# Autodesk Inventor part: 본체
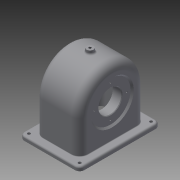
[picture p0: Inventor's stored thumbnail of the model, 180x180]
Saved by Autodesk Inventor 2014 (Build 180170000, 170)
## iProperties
Created: 2016-01
Part Number: 본체
Material: Generic
Document SubType Name: Modeling
Designer: 04
Density: 1 g/cm^3
Appearance: Default
Author: 04
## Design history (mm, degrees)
sketch "스케치1"
  geometry: L1 (-57, 0)-(-57, 64); L2 (57, 64)-(57, 0); L3 (57, 0)-(-57, 0); A1 r 57 centre (0, 64) between (57, 64) and (-57, 64); 2 further points
  constraints: 6 end point, 2 point on circle, 2 tangent, 1 centre point, 1 coincident, 1 midpoint, 1 parallel, 1 perpendicular, 1 vertical
  dimensions: "d0" = 64 distance of L1.start L1.end; "d2" = 114 distance of L2.end L1.start
extrude "돌출1" new body sketch "스케치1" stored distance "d3" = 77; taper "d4" = 0 deg
sketch "스케치3"
  geometry: L1 (-57, 0)-(-57, 64) reference; L2 (57, 0)-(-57, 0) reference; L3 (57, 64)-(57, 0) reference; L4 (51, 64)-(51, 0); L5 (-51, 0)-(-51, 64); A1 r 57 centre (0, 64) between (57, 64) and (-57, 64) reference; A2 r 51 centre (0, 64) between (51, 64) and (-51, 64); 1 further point
  constraints: 4 end point, 2 point on circle, 2 point on line, 1 centre point, 1 parallel, 1 perpendicular, 1 tangent
  dimensions: "d5" = 6 distance between parallel lines of L1 L5; "d6" = 6 distance between parallel lines of L3 L4
extrude "돌출2" cut sketch "스케치3" stored distance "d7" = 67; taper "d8" = 0 deg
sketch "스케치4"
  geometry: L1 (72, -6)-(72, -108) reference; L2 (72, -108)-(5, -108) reference; L3 (5, -108)-(5, -6) reference; L4 (5, -6)-(72, -6) reference; L5 (90.5, -127)-(-13.5, -127); L6 (-13.5, -127)-(-13.5, 13); L7 (-13.5, 13)-(90.5, 13); L8 (90.5, 13)-(90.5, -127); L9 (90.5, -127)-(-13.5, 13); L10 (-13.5, -127)-(90.5, 13); 1 further point
  constraints: 12 end point, 2 midpoint, 2 parallel, 1 horizontal, 1 perpendicular
  dimensions: "d9" = 104 distance of L6.end L7.end; "d10" = 140 distance of L5.end L6.end
extrude "돌출3" join sketch "스케치4" distance "d11" = 7; taper "d12" = 0 deg
sketch "스케치6"
  geometry: 1 further point
sketch "스케치7"
  geometry: C1 r 31 at (64, 0); A1 r 57 centre (64, 0) between (64, -57) and (64, 57) reference; 1 further point
  constraints: 1 centre point, 1 coincident
  dimensions: "d86" = 62 diameter of C1
extrude "돌출4" join sketch "스케치7" distance "d14" = 10; taper "d15" = 0 deg
sketch "스케치8"
  geometry: L1 (-33.5, 115)-(-33.5, 64) reference; L2 (-33.5, 64)-(-33.5, 0) reference; L3 (48.5, 33)-(48.5, 95) reference; L4 (48.5, 64)-(-33.5, 64); L5 (-38.5, 121)-(-38.5, 64) reference; L6 (-38.5, 64)-(-38.5, 7) reference; L7 (-38.5, 107.943)-(-19.5, 92); L8 (-19.5, 92)-(-19.5, 64); L9 (-19.5, 64)-(-38.5, 64); 3 further points
  constraints: 8 end point, 2 perpendicular, 2 point on line, 1 collinear, 1 midpoint
  dimensions: "d18" = 50 deg angle of L8 L7; "d19" = 19 distance between parallel lines of L5 L8; "d20" = 28 distance of L7.end L8.end
revolve "회전1" sketch "스케치8" stored, may be unused: angle "d21" = 90 deg
sketch "스케치9"
  geometry: L1 (-38.5, 121)-(-38.5, 64) reference; L2 (-38.5, 64)-(-38.5, 7) reference; L3 (48.5, 33)-(48.5, 95) reference; L4 (48.5, 64)-(-38.5, 64); L5 (-33.5, 103.747)-(-19.5, 92) reference; L6 (-38.5, 101.416)-(-35.5, 98.899); L7 (-38.5, 101.416)-(-38.5, 64); L8 (-35.5, 64)-(-35.5, 98.899); L9 (-38.5, 64)-(-35.5, 64); 2 further points
  constraints: 10 end point, 2 collinear, 2 parallel, 2 point on line, 1 midpoint, 1 perpendicular
  dimensions: "d22" = 5 distance between parallel lines of L5 L6; "d23" = 3 distance between parallel lines of L7 L8
revolve "회전2" sketch "스케치9" stored, may be unused: angle "d24" = 90 deg
sketch "스케치10"
  geometry: C1 r 31 at (0, 0) reference; C2 r 20 at (0, 0); 1 further point
  constraints: 1 centre point, 1 coincident
  dimensions: "d25" = 40 diameter of C2
extrude "돌출5" cut sketch "스케치10" stored distance "d26" = 10; taper "d27" = 0 deg
sketch "스케치11"
  geometry: C1 r 20 at (0, 0) reference; 2 further points
  constraints: 1 horizontal alignment
  dimensions: "d28" = 28 distance of C1.centre point (-28, 0)
sketch "스케치12"
  geometry: C1 r 20 at (0, 0) reference; 2 further points
  constraints: 1 horizontal alignment
  dimensions: "d29" = 24 distance of C1.centre point (24, 0)
hole "구멍1" sketch "스케치11" diameter "d30" = 2.459; stored, may be unused: countersink angle "d34" = 90 deg, drill point angle "d36" = 118 deg; dims "d31" = 7, "d32" = 4, "d33" = 2, "d35" = 9
hole "구멍2" sketch "스케치12" diameter "d37" = 2.459; stored, may be unused: countersink angle "d41" = 90 deg, drill point angle "d43" = 118 deg; dims "d38" = 6, "d39" = 4, "d40" = 2, "d42" = 8
node "작업 평면2"
sketch "스케치13"
  geometry: C1 r 6 at (-52, 70); 1 further point
  constraints: 1 centre point, 1 coincident
  dimensions: "d53" = 12 diameter of C1
extrude "돌출6" join sketch "스케치13" stored distance "d54" = 10; taper "d55" = 0 deg
sketch "스케치14"
  geometry: C1 r 6 at (0, 0) reference
hole "구멍3" sketch "스케치14" at (0, 0) diameter "d56" = 4.134; stored, may be unused: countersink angle "d60" = 90 deg, drill point angle "d62" = 118 deg; dims "d57" = 6, "d58" = 4, "d59" = 2, "d61" = 8
fillet "모깎기1" dims "d63" = 8, "d64" = 3, "d65" = 14
fillet "모깎기2" dims "d66" = 3, "d75" = 1
sketch "스케치15"
  geometry: A1 r 8 centre (-82.5, 5) between (-82.5, 13) and (-90.5, 5) reference; A2 r 8 centre (-82.5, -119) between (-90.5, -119) and (-82.5, -127) reference; A3 r 8 centre (5.5, -119) between (5.5, -127) and (13.5, -119) reference; A4 r 8 centre (5.5, 5) between (13.5, 5) and (5.5, 13) reference; 1 further point
hole "구멍4" sketch "스케치15" at (-82.5, -119), (5.5, -119), (5.5, 5), (-82.5, 5) diameter "d68" = 5; stored, may be unused: countersink angle "d72" = 90 deg, drill point angle "d74" = 118 deg; dims "d69" = 6, "d70" = 4, "d71" = 2, "d73" = 8
chamfer "모따기1" distance "d76" = 1; stored, may be unused: second distance "d77" = 2, angle "d78" = 45 deg
fillet "모깎기3" dims "d79" = 9
feature "엠보싱1" dims "d82" = 0.5, "d83" = 0
node "솔리드1"
pattern_circular "원형 패턴1" dims angle "d45" = 360 deg
pattern_circular "원형 패턴2" dims angle "d48" = 360 deg
sketch "스케치16"
  geometry: L1 (68.5, 64)-(-19.5, 64) reference; L2 (63, 0)-(63, 56) reference; L3 (68.5, 64)-(76.5, 64) reference; L4 (38.421, 32.03)-(10.579, 32.03); L5 (10.579, 32.03)-(10.579, 35.97); L6 (10.579, 35.97)-(38.421, 35.97); L7 (38.421, 35.97)-(38.421, 32.03); 1 further point
  constraints: 2 other
other parameters: "d51" = -127
